// Mitsubishi GX Works2 project: 49.停车场监控（SFWR命令）   PLC: FX3U/FX3UC

PROGRAM MAIN
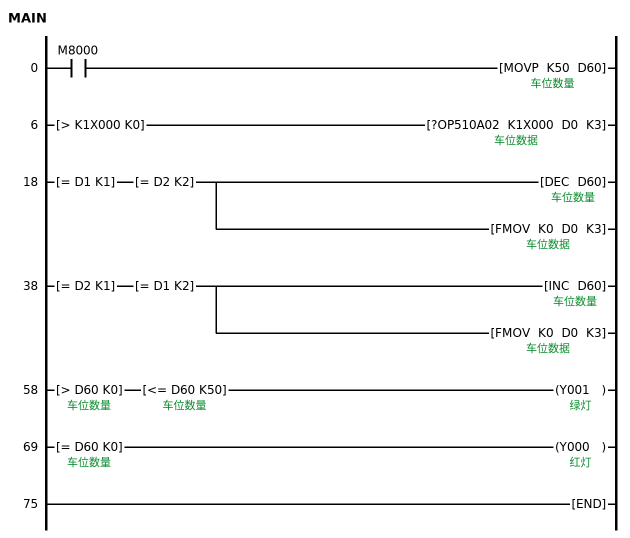
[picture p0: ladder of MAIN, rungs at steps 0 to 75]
0     LD      M8000
      MOVP    K50 D60  ; 车位数量
        [note] 预存50个车位
6     LD>     K1X000 K0  ; 感应开关
      ?OP510A02 K1X000 D0 K3  ; 车位数据
18    LD=     D1 K1
      AND=    D2 K2
      DEC     D60
        [note] 车位数自减一
      FMOV    K0 D0 K3
        [note] 自减一后把D0-D2清零
38    LD=     D2 K1
      AND=    D1 K2
      INC     D60
        [note] 车位数自加一
      FMOV    K0 D0 K3
        [note] 自加一后把D0-D2清零
58    LD>     D60 K0  ; 车位数量
      AND<=   D60 K50  ; 车位数量
      OUT     Y001  ; 绿灯
69    LD=     D60 K0  ; 车位数量
      OUT     Y000  ; 红灯
75    END
END_PROGRAM

// device comments not shown above
M0  ; 运行标识
M1  ; 运行标识
D50  ; 车位数
